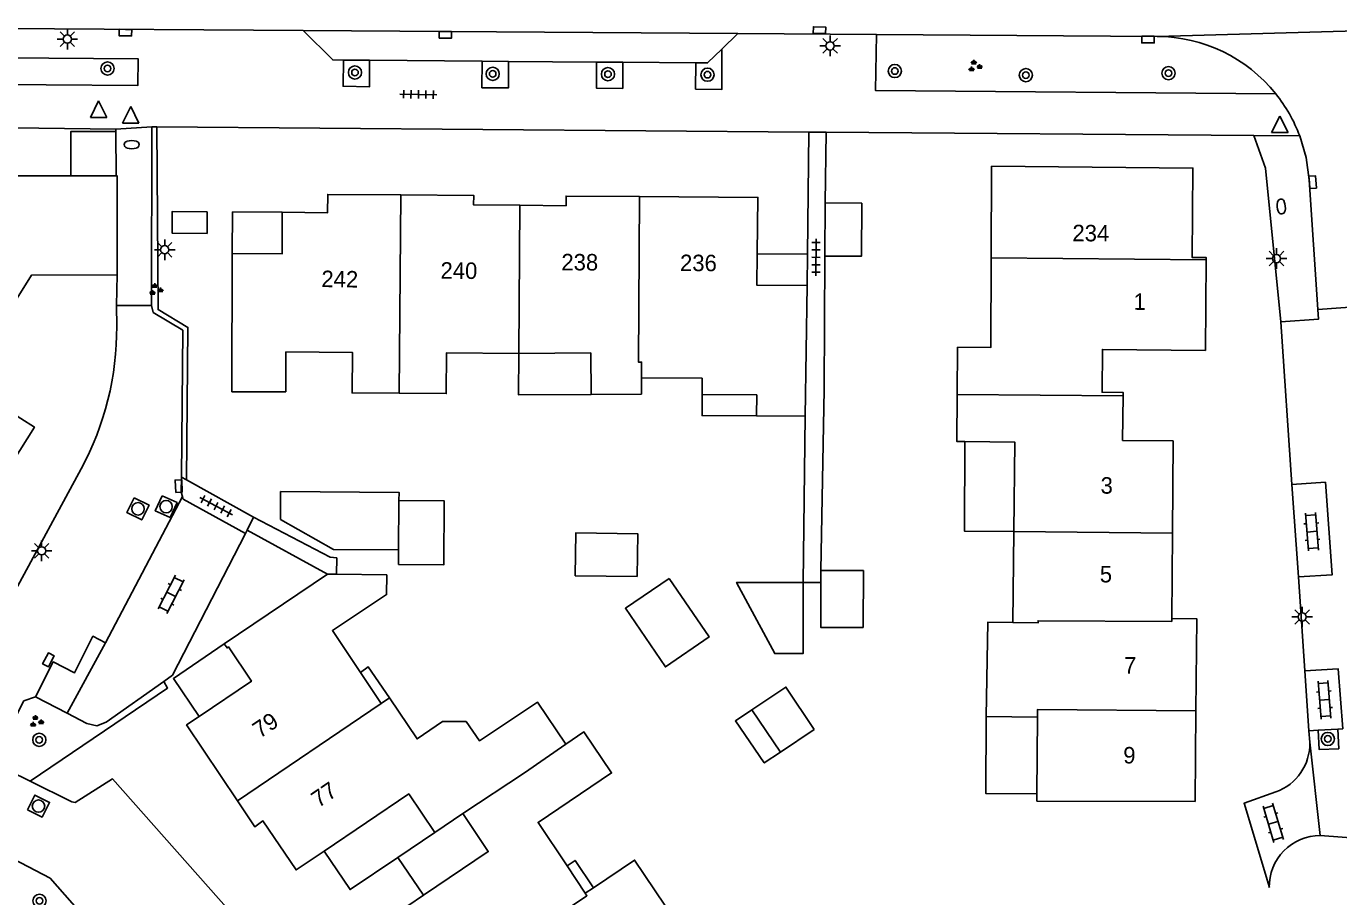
# Model space of a CAD drawing. Extents: x 131000 to 133013, y 393000 to 396501.
# Drawn here: x 131097 to 131176.6, y 394889.4 to 394942.2 of the extents above; entities that cross this region are included whole.
import ezdxf

# ---------------------------------------------------------------- set-up
doc = ezdxf.new("R2010")
doc.units = 0
for name, color, linetype in [('gg-afsc-erfafscheiding', 7, 'Continuous'), ('gg-afsc-hekwerk', 7, 'Continuous'), ('gg-anno-huisnummerreeks BGT', 7, 'Continuous'), ('gg-bbg-bijgebouw', 7, 'Continuous'), ('gg-bbg-gedigitaliseerde bebouwing', 7, 'Continuous'), ('gg-bbg-gedigitaliseerde bijgebouw', 7, 'Continuous'), ('gg-bbg-hoofdgebouw', 7, 'Continuous'), ('gg-bbg-luifel en loopbrug', 7, 'Continuous'), ('gg-bbg-tussenscheiding', 7, 'Continuous'), ('gg-knt-verharding', 7, 'Continuous'), ('gg-knt-verharding nz', 7, 'Continuous'), ('gt-grn-vlakafsluiter', 7, 'Continuous'), ('gt-grn-weggrens', 7, 'Continuous'), ('gt-symb-boom', 7, 'Continuous'), ('gt-symb-brandkraan', 7, 'Continuous'), ('gt-symb-groenvak', 7, 'Continuous'), ('gt-symb-klinker verharding', 7, 'Continuous'), ('gt-symb-kolk', 7, 'Continuous'), ('gt-symb-kolk center center', 7, 'Continuous'), ('gt-symb-lichtmast', 7, 'Continuous'), ('gt-symb-rioolschacht', 7, 'Continuous'), ('gt-symb-tegel verharding', 7, 'Continuous'), ('gt-symb-waterafsluiter', 7, 'Continuous')]:
    doc.layers.add(name, color=color, linetype=linetype)

# ---------------------------------------------------------------- blocks, each defined once
blk = doc.blocks.new('gt0-BOOM')
at = {"layer": 'gt-symb-boom'}
for radius in [0.4, 0.2]:
    blk.add_circle((0, 0), radius, dxfattribs=at)
blk = doc.blocks.new('gt0-KOLK')
at = {"layer": 'gt-symb-kolk'}
blk.add_lwpolyline([(0, 0), (0.375, 0), (0.375, 0.4), (-0.375, 0.4), (-0.375, 0), (0, 0)], dxfattribs=at)
blk = doc.blocks.new('gt0-LMAST')
at = {"layer": 'gt-symb-lichtmast'}
for p, q in [((-0.182, 0.173), (-0.447, 0.438)), ((-0.005, 0.246), (-0.005, 0.621)), ((0.172, 0.173), (0.437, 0.438)), ((-0.255, -0.004), (-0.63, -0.004)), ((-0.182, -0.181), (-0.447, -0.446)), ((-0.005, -0.254), (-0.005, -0.629)), ((0.437, -0.446), (0.172, -0.181)), ((0.245, -0.004), (0.62, -0.004))]:
    blk.add_line(p, q, dxfattribs=at)
blk.add_circle((-0.005, -0.004), 0.25, dxfattribs=at)
blk = doc.blocks.new('gt0-KL1')
at = {"layer": 'gt-symb-klinker verharding'}
for p, q in [((-1.15, 0.3), (1.15, 0.3)), ((-1, -0.3), (-1, 0.3)), ((-0.5, 0.3), (-0.5, 0.45)), ((0, -0.3), (0, 0.3)), ((0.5, 0.3), (0.5, 0.45)), ((1, -0.3), (1, 0.3)), ((-1.15, -0.3), (1.15, -0.3)), ((-0.5, -0.45), (-0.5, -0.3)), ((0.5, -0.45), (0.5, -0.3))]:
    blk.add_line(p, q, dxfattribs=at)
blk = doc.blocks.new('gt0-GRVAK')
at = {"layer": 'gt-symb-groenvak'}
for p, q in [((-0.11, 0.189), (-0.228, 0.24)), ((-0.182, 0.153), (0.088, 0.153)), ((-0.091, 0.211), (-0.156, 0.322)), ((-0.047, 0.214), (-0.047, 0.393)), ((-0.004, 0.211), (0.061, 0.322)), ((0.015, 0.189), (0.133, 0.24)), ((0.262, -0.052), (0.197, 0.059)), ((0.305, -0.049), (0.305, 0.13)), ((0.349, -0.052), (0.414, 0.059)), ((-0.245, -0.228), (-0.363, -0.177)), ((-0.318, -0.264), (-0.047, -0.264)), ((-0.226, -0.206), (-0.291, -0.095)), ((-0.183, -0.203), (-0.183, -0.024)), ((-0.139, -0.206), (-0.074, -0.095)), ((-0.12, -0.228), (-0.002, -0.177)), ((0.243, -0.074), (0.125, -0.023)), ((0.17, -0.11), (0.441, -0.11)), ((0.368, -0.074), (0.486, -0.023))]:
    blk.add_line(p, q, dxfattribs=at)
blk = doc.blocks.new('gt0-RS')
at = {"layer": 'gt-symb-rioolschacht'}
blk.add_lwpolyline([(-0.5, -0.5), (0.5, -0.5), (0.5, 0.5), (-0.5, 0.5)], close=True, dxfattribs=at)
blk.add_circle((0, 0), 0.375, dxfattribs=at)
blk = doc.blocks.new('gt0-WAFSL')
at = {"layer": 'gt-symb-waterafsluiter'}
for p, q in [((-0.5, -0.333), (0, 0.667)), ((0, 0.667), (0.5, -0.333)), ((0.5, -0.333), (-0.5, -0.333))]:
    blk.add_line(p, q, dxfattribs=at)
blk = doc.blocks.new('gt0-BR')
at = {"layer": 'gt-symb-brandkraan'}
for centre, radius, start, end in [((-0.244, 0), 0.206, 107.56694, 252.43307), ((0.599, -2.664), 3, 106.89205, 107.56694), ((0, -0.691), 0.938, 73.10799, 106.89205), ((-0.599, -2.664), 3, 72.43309, 73.10799), ((0.244, 0), 0.206, 287.56695, 72.43309), ((0.599, 2.664), 3, 252.43307, 253.10797), ((0, 0.691), 0.938, 253.10797, 286.89206), ((-0.599, 2.664), 3, 286.89206, 287.56695)]:
    blk.add_arc(centre, radius, start, end, dxfattribs=at)
blk = doc.blocks.new('gt0-TEG1')
at = {"layer": 'gt-symb-tegel verharding'}
for p, q in [((-1.125, 0), (1.125, 0)), ((-0.9, -0.25), (-0.9, 0.25)), ((-0.45, -0.25), (-0.45, 0.25)), ((0, -0.25), (0, 0.25)), ((0.45, -0.25), (0.45, 0.25)), ((0.9, -0.25), (0.9, 0.25))]:
    blk.add_line(p, q, dxfattribs=at)
blk = doc.blocks.new('gt0-KOLKCC')
at = {"layer": 'gt-symb-kolk center center'}
blk.add_lwpolyline([(-0.375, 0.2), (0.375, 0.2), (0.375, -0.2), (-0.375, -0.2)], close=True, dxfattribs=at)

msp = doc.modelspace()

# ---------------------------------------------------------------- linework, layer by layer
at = {"layer": 'gg-afsc-erfafscheiding'}
for p, q in [((131145.43, 394931.496), (131145.504, 394935.787)), ((131145.376, 394920.186), (131145.421, 394928.278)), ((131145.376, 394920.186), (131145.184, 394909.212)), ((131144.229, 394918.564), (131144.104, 394908.493)), ((131110.755, 394912.448), (131106.692, 394914.712)), ((131144.104, 394908.493), (131145.184, 394908.493))]:
    msp.add_line(p, q, dxfattribs=at)
for points in [[(131106.692, 394914.712), (131106.787, 394923.953), (131104.976, 394925.029), (131104.899, 394936.11)], [(131115.807, 394908.979), (131115.813, 394909.977), (131115.422, 394910.018), (131110.755, 394912.448)]]:
    msp.add_lwpolyline(points, dxfattribs=at)
at = {"layer": 'gg-afsc-hekwerk'}
msp.add_line((131102.421, 394935.836), (131102.42, 394935.972), dxfattribs=at)
msp.add_lwpolyline([(131102.42, 394935.972), (131082.167, 394936.238), (131079.651, 394936.699)], dxfattribs=at)
at = {"layer": 'gg-bbg-bijgebouw'}
for q in [(131145.421, 394928.278), (131147.659, 394931.49)]:
    msp.add_line((131145.43, 394931.496), q, dxfattribs=at)
at = {"layer": 'gg-bbg-gedigitaliseerde bebouwing'}
for p, q in [((131155.531, 394933.722), (131155.505, 394928.17)), ((131137.983, 394920.881), (131134.3, 394920.901)), ((131134.3, 394920.901), (131134.3, 394919.91)), ((131137.976, 394919.875), (131137.983, 394920.881)), ((131134.3, 394919.91), (131131.239, 394919.89)), ((131144.229, 394918.564), (131141.281, 394918.583)), ((131156.886, 394911.58), (131156.83, 394906.05)), ((131117.246, 394903.035), (131118.514, 394901.145)), ((131118.514, 394901.145), (131119.011, 394901.481)), ((131155.204, 394900.367), (131158.313, 394900.308)), ((131158.313, 394900.308), (131158.283, 394895.672)), ((131129.783, 394891.299), (131130.89, 394889.64)), ((131130.89, 394889.64), (131131.39, 394889.97))]:
    msp.add_line(p, q, dxfattribs=at)
for points in [[(131155.505, 394928.17), (131155.48, 394922.73), (131153.47, 394922.75), (131153.445, 394919.88)], [(131119.59, 394919.96), (131116.74, 394919.98), (131116.76, 394922.44), (131112.73, 394922.47), (131112.721, 394920.037)], [(131126.86, 394922.375), (131122.47, 394922.4), (131122.45, 394919.94), (131119.59, 394919.96)], [(131131.239, 394919.89), (131131.222, 394922.404), (131126.86, 394922.375)], [(131141.281, 394918.583), (131141.289, 394919.853), (131137.976, 394919.875)], [(131153.445, 394919.88), (131153.42, 394917.04), (131153.916, 394917.034)], [(131153.916, 394917.034), (131156.94, 394917), (131156.886, 394911.58)], [(131118.852, 394908.944), (131118.838, 394907.754), (131115.548, 394905.568), (131117.246, 394903.035)], [(131156.83, 394906.05), (131155.313, 394906.079), (131155.204, 394900.367)], [(131119.011, 394901.481), (131120.684, 394898.998), (131122.235, 394900.045), (131123.663, 394900.06), (131124.474, 394898.873), (131127.981, 394901.234), (131129.703, 394898.677)], [(131129.703, 394898.677), (131130.804, 394899.418), (131132.486, 394896.941), (131128.022, 394893.938), (131129.783, 394891.299)], [(131158.283, 394895.672), (131158.28, 394895.23), (131167.885, 394895.212)], [(131131.39, 394889.97), (131133.878, 394891.647), (131136.97, 394887.058)]]:
    msp.add_lwpolyline(points, dxfattribs=at)
at = {"layer": 'gg-bbg-gedigitaliseerde bijgebouw'}
for p, q in [((131119.589, 394913.446), (131119.568, 394910.465)), ((131119.568, 394910.465), (131119.562, 394909.568)), ((131145.184, 394908.493), (131145.184, 394909.212)), ((131140.996, 394900.756), (131142.721, 394898.196)), ((131142.721, 394898.196), (131144.777, 394899.57))]:
    msp.add_line(p, q, dxfattribs=at)
for points in [[(131147.659, 394931.49), (131147.641, 394928.269), (131145.421, 394928.278)], [(131119.562, 394909.568), (131122.303, 394909.549), (131122.331, 394913.426), (131119.589, 394913.446)], [(131134.04, 394908.84), (131130.275, 394908.888), (131130.308, 394911.489), (131134.073, 394911.44), (131134.04, 394908.84)], [(131147.741, 394905.75), (131147.755, 394909.201), (131145.184, 394909.212)], [(131144.104, 394908.493), (131144.104, 394904.169), (131142.379, 394904.169), (131140.063, 394908.493), (131144.104, 394908.493)], [(131145.184, 394908.493), (131145.182, 394905.75), (131147.741, 394905.75)], [(131144.777, 394899.57), (131143.061, 394902.137), (131140.996, 394900.756)]]:
    msp.add_lwpolyline(points, dxfattribs=at)
at = {"layer": 'gg-bbg-hoofdgebouw'}
for p, q in [((131099.688, 394933.139), (131102.442, 394933.139)), ((131144.342, 394926.485), (131144.229, 394918.564)), ((131166.508, 394911.484), (131166.556, 394917.067)), ((131166.463, 394906.304), (131166.508, 394911.484)), ((131115.249, 394908.986), (131108.99, 394904.764)), ((131115.807, 394908.979), (131115.249, 394908.986)), ((131118.852, 394908.944), (131115.807, 394908.979)), ((131167.885, 394895.212), (131167.93, 394900.698)), ((131123.455, 394894.467), (131121.757, 394893.323))]:
    msp.add_line(p, q, dxfattribs=at)
for points in [[(131155.531, 394933.722), (131167.742, 394933.616), (131167.695, 394928.197), (131168.556, 394928.189), (131168.555, 394928.041)], [(131087.989, 394923.485), (131086.238, 394924.584), (131091.664, 394933.24), (131093.804, 394931.889), (131094.615, 394933.139), (131099.688, 394933.139)], [(131102.5, 394927.137), (131102.503, 394933.139), (131102.442, 394933.139)], [(131119.71, 394931.985), (131115.263, 394932.013), (131115.252, 394930.893), (131112.508, 394930.931)], [(131126.926, 394931.36), (131124.102, 394931.389), (131124.125, 394931.957), (131119.71, 394931.985)], [(131134.182, 394931.884), (131129.726, 394931.912), (131129.723, 394931.332), (131126.926, 394931.36)], [(131141.313, 394928.416), (131141.355, 394931.839), (131134.182, 394931.884)], [(131112.508, 394930.931), (131112.493, 394928.408), (131109.478, 394928.432)], [(131109.478, 394928.432), (131109.451, 394920.048), (131112.721, 394920.037)], [(131144.342, 394926.485), (131141.289, 394926.519), (131141.313, 394928.416)], [(131168.555, 394928.041), (131168.507, 394922.56), (131162.257, 394922.614), (131162.234, 394920.02), (131163.506, 394920.009), (131163.504, 394919.808)], [(131102.5, 394927.137), (131097.301, 394927.121), (131094.628, 394922.875), (131096.415, 394921.72), (131094.975, 394919.486)], [(131094.975, 394919.486), (131097.474, 394917.912), (131095.141, 394914.209), (131094.404, 394914.656), (131093.142, 394912.635)], [(131163.504, 394919.808), (131163.481, 394917.094), (131166.556, 394917.067)], [(131167.93, 394900.698), (131167.975, 394906.283), (131166.463, 394906.304)], [(131108.99, 394904.764), (131109.158, 394904.516), (131109.241, 394904.572), (131110.639, 394902.499), (131107.475, 394900.365)], [(131109.784, 394895.253), (131106.701, 394899.843), (131107.475, 394900.365)], [(131121.757, 394893.323), (131120.184, 394895.658), (131115.046, 394892.196)], [(131115.046, 394892.196), (131113.351, 394891.054), (131111.33, 394894.03), (131110.843, 394893.676), (131109.784, 394895.253)], [(131121.074, 394889.514), (131125.007, 394892.165), (131123.455, 394894.467)], [(131122.254, 394883.645), (131119.168, 394888.23), (131121.074, 394889.514)]]:
    msp.add_lwpolyline(points, dxfattribs=at)
at = {"layer": 'gg-bbg-luifel en loopbrug'}
for p, q in [((131102.442, 394933.139), (131102.421, 394935.836)), ((131141.313, 394928.416), (131144.364, 394928.397)), ((131144.364, 394928.397), (131144.342, 394926.485)), ((131119.522, 394891.817), (131121.757, 394893.323)), ((131121.074, 394889.514), (131119.522, 394891.817))]:
    msp.add_line(p, q, dxfattribs=at)
for points in [[(131099.688, 394933.139), (131099.688, 394935.836), (131102.421, 394935.836)], [(131107.956, 394930.967), (131107.946, 394929.652), (131105.83, 394929.669), (131105.84, 394930.984), (131107.956, 394930.967)], [(131109.478, 394928.432), (131109.498, 394930.955), (131112.508, 394930.931)], [(131131.239, 394919.89), (131126.842, 394919.861), (131126.86, 394922.375)], [(131141.281, 394918.583), (131137.968, 394918.604), (131137.976, 394919.875)], [(131156.886, 394911.58), (131153.881, 394911.6), (131153.916, 394917.034)], [(131119.589, 394913.446), (131119.593, 394913.941), (131112.405, 394913.994), (131112.393, 394912.309), (131115.617, 394910.493), (131119.568, 394910.465)], [(131135.974, 394908.733), (131138.402, 394905.181), (131135.747, 394903.367), (131133.32, 394906.919), (131135.974, 394908.733)], [(131108.99, 394904.764), (131105.908, 394902.658), (131107.475, 394900.365)], [(131119.011, 394901.481), (131117.725, 394903.362), (131117.246, 394903.035)], [(131140.996, 394900.756), (131139.998, 394900.089), (131141.742, 394897.541), (131142.721, 394898.196)], [(131158.283, 394895.672), (131155.174, 394895.692), (131155.204, 394900.367)], [(131119.522, 394891.817), (131116.62, 394889.861), (131115.046, 394892.196)], [(131131.39, 394889.97), (131130.272, 394891.629), (131129.783, 394891.299)]]:
    msp.add_lwpolyline(points, dxfattribs=at)
at = {"layer": 'gg-bbg-tussenscheiding'}
for p, q in [((131119.59, 394919.96), (131119.71, 394931.985)), ((131126.86, 394922.375), (131126.926, 394931.36)), ((131155.505, 394928.17), (131168.555, 394928.041)), ((131153.445, 394919.88), (131163.504, 394919.808)), ((131156.886, 394911.58), (131166.508, 394911.484)), ((131109.784, 394895.253), (131118.514, 394901.145))]:
    msp.add_line(p, q, dxfattribs=at)
for points in [[(131134.3, 394920.901), (131134.3, 394921.85), (131134.11, 394921.85), (131134.182, 394931.884)], [(131156.83, 394906.05), (131158.35, 394906.03), (131158.35, 394906.16), (131166.464, 394906.127), (131166.463, 394906.304)], [(131158.313, 394900.308), (131158.316, 394900.78), (131167.93, 394900.698)], [(131123.455, 394894.467), (131127.21, 394896.95), (131129.703, 394898.677)], [(131122.254, 394883.645), (131130.991, 394889.49), (131130.89, 394889.64)]]:
    msp.add_lwpolyline(points, dxfattribs=at)
at = {"layer": 'gg-knt-verharding'}
for p, q in [((131113.775, 394941.95), (131095.683, 394942.072)), ((131140.139, 394941.772), (131139.162, 394940.825)), ((131148.557, 394941.715), (131140.139, 394941.772)), ((131148.557, 394941.715), (131165.573, 394941.601)), ((131117.805, 394940.152), (131116.214, 394940.164)), ((131124.627, 394940.099), (131117.805, 394940.152)), ((131126.239, 394940.086), (131124.627, 394940.099)), ((131131.571, 394940.044), (131126.239, 394940.086)), ((131133.168, 394940.032), (131131.571, 394940.044)), ((131137.592, 394939.998), (131133.168, 394940.032)), ((131104.599, 394936.112), (131104.57, 394925.279)), ((131104.899, 394936.11), (131104.599, 394936.112)), ((131144.449, 394935.796), (131104.899, 394936.11)), ((131144.449, 394935.796), (131144.364, 394928.397)), ((131171.439, 394935.581), (131145.504, 394935.787)), ((131102.5, 394927.137), (131102.46, 394925.274)), ((131102.46, 394925.274), (131104.57, 394925.279)), ((131102.46, 394925.274), (131102.469, 394924.013)), ((131180.398, 394925.4), (131175.317, 394925.03)), ((131173.073, 394924.28), (131173.753, 394914.423)), ((131106.692, 394914.712), (131106.394, 394914.878)), ((131173.753, 394914.423), (131174.14, 394908.823)), ((131110.275, 394911.449), (131110.371, 394911.649)), ((131110.371, 394911.649), (131115.249, 394908.986)), ((131174.14, 394908.823), (131174.533, 394903.12)), ((131174.533, 394903.12), (131174.783, 394899.498)), ((131099.455, 394900.566), (131097.54, 394901.54)), ((131174.783, 394899.498), (131174.832, 394898.793)), ((131176.527, 394899.598), (131175.337, 394899.53)), ((131095.894, 394897.092), (131097.208, 394896.437)), ((131175.459, 394893.132), (131183.399, 394892.567))]:
    msp.add_line(p, q, dxfattribs=at)
for points in [[(131095.683, 394942.072), (131095.633, 394940.294), (131103.768, 394940.237), (131103.749, 394938.626), (131081.487, 394938.78), (131079.42, 394939.189), (131077.42, 394939.853), (131074.851, 394940.934), (131072.245, 394941.951)], [(131116.214, 394940.164), (131115.575, 394940.169), (131113.775, 394941.95)], [(131172.766, 394938.124), (131148.498, 394938.311), (131148.557, 394941.715)], [(131137.592, 394939.998), (131137.58, 394938.404), (131139.175, 394938.387), (131139.162, 394940.825)], [(131139.162, 394940.825), (131138.302, 394939.992), (131137.592, 394939.998)], [(131116.214, 394940.164), (131116.202, 394938.575), (131117.792, 394938.533), (131117.805, 394940.152)], [(131124.627, 394940.099), (131124.614, 394938.484), (131126.226, 394938.478), (131126.239, 394940.086)], [(131131.571, 394940.044), (131131.559, 394938.46), (131133.156, 394938.448), (131133.168, 394940.032)], [(131173.073, 394924.28), (131172.157, 394933.603), (131171.439, 394935.581)], [(131174.225, 394935.559), (131174.61, 394934.246), (131174.8, 394932.891), (131175.317, 394925.03)], [(131106.394, 394914.878), (131106.485, 394923.783), (131104.677, 394924.858), (131104.57, 394925.279)], [(131175.317, 394925.03), (131175.356, 394924.442), (131173.073, 394924.28)], [(131100.312, 394915.378), (131096.335, 394908.02), (131092.696, 394902.763)], [(131106.394, 394914.878), (131106.384, 394913.952), (131106.456, 394913.697)], [(131110.275, 394911.449), (131106.5, 394913.542), (131106.456, 394913.697)], [(131105.326, 394902.489), (131105.85, 394902.861), (131110.275, 394911.449)], [(131097.208, 394896.437), (131105.548, 394902.076), (131105.326, 394902.489)], [(131105.326, 394902.489), (131101.833, 394900.007), (131101.252, 394899.801), (131100.65, 394899.931), (131099.455, 394900.566)], [(131097.54, 394901.54), (131096.837, 394901.304), (131095.422, 394898.497), (131095.894, 394897.092)], [(131175.337, 394899.53), (131175.408, 394898.353), (131176.586, 394898.4), (131176.527, 394899.598)], [(131125.568, 394869.291), (131123.998, 394871.979), (131102.218, 394896.573), (131099.949, 394895.133), (131099.742, 394895.175), (131097.208, 394896.437)], [(131172.771, 394895.781), (131170.852, 394895.097), (131172.38, 394889.988)], [(131101.1, 394887.53), (131098.426, 394890.554), (131093.953, 394892.878), (131093.58, 394892.899)]]:
    msp.add_lwpolyline(points, dxfattribs=at)
for centre, radius, start, end in [((131165.504, 394932.279), 9.323, 38.82965, 89.57334), ((131165.374, 394932.222), 9.459, 20.65755, 38.60583), ((131084.549, 394923.902), 17.92, 331.59592, 0.35345), ((131171.73, 394898.705), 3.104, 289.60414, 1.63108), ((131175.45, 394890.062), 3.071, 89.82505, 181.37183)]:
    msp.add_arc(centre, radius, start, end, dxfattribs=at)
at = {"layer": 'gg-knt-verharding nz'}
for p, q in [((131140.139, 394941.772), (131113.775, 394941.95)), ((131101.786, 394904.817), (131106.456, 394913.697)), ((131175.337, 394899.53), (131174.783, 394899.498))]:
    msp.add_line(p, q, dxfattribs=at)
for points in [[(131173.753, 394914.423), (131175.78, 394914.567), (131176.192, 394908.951), (131174.14, 394908.823)], [(131097.54, 394901.54), (131098.619, 394903.67), (131099.903, 394902.998), (131101.021, 394905.22), (131101.786, 394904.817)], [(131174.533, 394903.12), (131176.565, 394903.239), (131176.831, 394899.615), (131176.527, 394899.598)]]:
    msp.add_lwpolyline(points, dxfattribs=at)
at = {"layer": 'gt-grn-vlakafsluiter'}
msp.add_line((131174.832, 394898.793), (131175.459, 394893.132), dxfattribs=at)
at = {"layer": 'gt-grn-weggrens'}
for p, q in [((131165.573, 394941.601), (131187.362, 394942.213)), ((131104.599, 394936.112), (131102.42, 394935.972)), ((131145.504, 394935.787), (131144.449, 394935.796)), ((131174.225, 394935.559), (131171.439, 394935.581)), ((131110.371, 394911.649), (131110.755, 394912.448)), ((131099.455, 394900.566), (131101.786, 394904.817))]:
    msp.add_line(p, q, dxfattribs=at)

# ---------------------------------------------------------------- block references
at = {"layer": 'gt-symb-boom'}
for p in [(131101.913, 394939.654), (131149.662, 394939.499), (131116.919, 394939.411), (131125.272, 394939.323), (131132.264, 394939.309), (131138.299, 394939.276), (131157.615, 394939.252), (131166.263, 394939.371), (131097.77, 394898.939), (131175.925, 394898.996), (131097.78, 394889.18)]:
    msp.add_blockref('gt0-BOOM', p, dxfattribs=at)
at = {"layer": 'gt-symb-brandkraan'}
msp.add_blockref('gt0-BR', (131103.378, 394935.034), dxfattribs=at)
at = {"layer": 'gt-symb-brandkraan', "rotation": -85.12211913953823}
msp.add_blockref('gt0-BR', (131173.103, 394931.283), dxfattribs=at)
at = {"layer": 'gt-symb-groenvak'}
for p in [(131154.503, 394939.788), (131104.816, 394926.236), (131097.578, 394900.049)]:
    msp.add_blockref('gt0-GRVAK', p, dxfattribs=at)
at = {"layer": 'gt-symb-klinker verharding'}
for p, rotation in [((131174.966, 394911.567), -85.58371655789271), ((131105.766, 394907.763), 62.74312821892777), ((131175.726, 394901.375), -85.58371655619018), ((131172.616, 394893.91), 106.67729393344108)]:
    msp.add_blockref('gt0-KL1', p, dxfattribs=dict(at, rotation=rotation))
at = {"layer": 'gt-symb-kolk'}
for p, rotation in [((131103, 394942.025), 179.71352348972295), ((131122.402, 394941.895), 179.88540859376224), ((131145.092, 394941.773), -0.802088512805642), ((131165.022, 394941.605), 179.6562294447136), ((131174.807, 394932.747), -85.75513794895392), ((131098.497, 394903.695), 61.974683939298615)]:
    msp.add_blockref('gt0-KOLK', p, dxfattribs=dict(at, rotation=rotation))
at = {"layer": 'gt-symb-kolk center center', "rotation": 92.63638190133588}
msp.add_blockref('gt0-KOLKCC', (131106.228, 394914.333), dxfattribs=at)
at = {"layer": 'gt-symb-lichtmast'}
for p in [(131099.478, 394941.437), (131145.741, 394941.026), (131105.383, 394928.665), (131172.818, 394928.127), (131097.919, 394910.406), (131174.378, 394906.396)]:
    msp.add_blockref('gt0-LMAST', p, dxfattribs=at)
at = {"layer": 'gt-symb-rioolschacht'}
for p, rotation in [((131103.758, 394912.949), -116.10382499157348), ((131105.465, 394913.083), -114.771138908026), ((131097.723, 394894.925), -26.872538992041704)]:
    msp.add_blockref('gt0-RS', p, dxfattribs=dict(at, rotation=rotation))
at = {"layer": 'gt-symb-tegel verharding'}
for p, rotation in [((131120.769, 394938.081), -0.8593722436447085), ((131144.881, 394928.201), -90.17188682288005), ((131108.492, 394913.116), -27.974729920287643)]:
    msp.add_blockref('gt0-TEG1', p, dxfattribs=dict(at, rotation=rotation))
at = {"layer": 'gt-symb-waterafsluiter'}
for p in [(131101.372, 394937.017), (131103.318, 394936.671), (131173.019, 394936.103)]:
    msp.add_blockref('gt0-WAFSL', p, dxfattribs=at)

# ---------------------------------------------------------------- texts
at = {"layer": 'gg-anno-huisnummerreeks BGT'}
for s, rotation, p in [('234', 359.5, (131160.432, 394929.179)), ('240', 359.4, (131122.104, 394926.909)), ('238', 359.7, (131129.437, 394927.412)), ('236', 359.7, (131136.633, 394927.367)), ('242', 359.2, (131114.876, 394926.398)), ('1', 359.5, (131164.141, 394925.019)), ('3', 359.5, (131162.141, 394913.872)), ('5', 359.5, (131162.094, 394908.49)), ('7', 359.5, (131163.56, 394902.963)), ('79', 33.9, (131111.146, 394899.006)), ('9', 359.5, (131163.516, 394897.513)), ('77', 34.2, (131114.707, 394894.794))]:
    msp.add_text(s, height=1, rotation=rotation, dxfattribs=at).set_placement(p)

doc.saveas('drawing.dxf')
